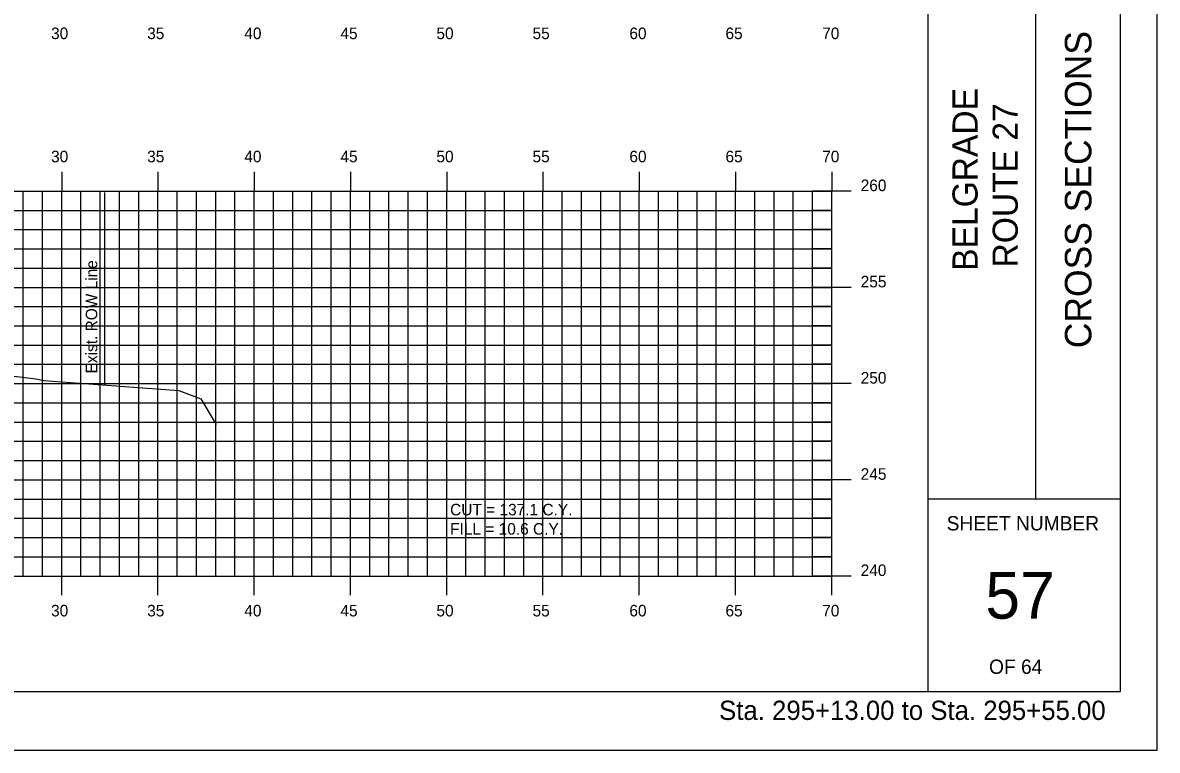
# Model space of a CAD drawing. Extents: x 859575 to 859745, y 366268 to 366378.
# Drawn here: x 859685.8 to 859744.7, y 366268.2 to 366306 of the extents above; entities that cross this region are included whole.
import ezdxf

# ---------------------------------------------------------------- set-up
doc = ezdxf.new("R2010")
doc.units = 0
for name, color, linetype in [('ANNOTATION', 7, 'Continuous'), ('BORDER', 7, 'Continuous'), ('E_ROW_Line', 7, 'Continuous'), ('H_V ANNOTATION', 7, 'Continuous'), ('HIGHWAY_TITLE', 7, 'Continuous'), ('MAJOR', 7, 'Continuous'), ('MINOR', 7, 'Continuous'), ('PLOT BOUNDARY', 7, 'Continuous'), ('S_Roadway_Centerline', 7, 'Continuous')]:
    doc.layers.add(name, color=color, linetype=linetype)

msp = doc.modelspace()

# ---------------------------------------------------------------- linework, layer by layer
at = {"layer": 'BORDER'}
for p, q in [((859732.797, 366271.236), (859732.797, 366376.239)), ((859742.797, 366271.236), (859742.797, 366376.236)), ((859738.388, 366281.239), (859738.388, 366316.239)), ((859732.797, 366281.239), (859742.797, 366281.239)), ((859582.797, 366271.236), (859742.797, 366271.236))]:
    msp.add_line(p, q, dxfattribs=at)
at = {"layer": 'E_ROW_Line'}
msp.add_line((859690.047, 366287.162), (859690.047, 366297.162), dxfattribs=at)
at = {"layer": 'MAJOR'}
for p, q in [((859687.797, 366298.238), (859687.797, 366297.236)), ((859692.797, 366298.238), (859692.797, 366297.236)), ((859697.797, 366298.238), (859697.797, 366297.236)), ((859702.797, 366298.238), (859702.797, 366297.236)), ((859707.797, 366298.238), (859707.797, 366297.236)), ((859712.797, 366298.238), (859712.797, 366297.236)), ((859717.797, 366298.238), (859717.797, 366297.236)), ((859722.797, 366298.238), (859722.797, 366297.236)), ((859727.797, 366298.238), (859727.797, 366297.236)), ((859587.797, 366297.236), (859727.797, 366297.236)), ((859587.797, 366297.236), (859727.797, 366297.236)), ((859687.797, 366277.236), (859687.797, 366297.236)), ((859692.797, 366277.236), (859692.797, 366297.236)), ((859697.797, 366277.236), (859697.797, 366297.236)), ((859702.797, 366277.236), (859702.797, 366297.236)), ((859707.797, 366277.236), (859707.797, 366297.236)), ((859712.797, 366277.236), (859712.797, 366297.236)), ((859717.797, 366277.236), (859717.797, 366297.236)), ((859722.797, 366277.236), (859722.797, 366297.236)), ((859728.799, 366297.236), (859726.795, 366297.236)), ((859727.797, 366277.236), (859727.797, 366297.236)), ((859727.797, 366277.236), (859727.797, 366297.236)), ((859587.797, 366292.236), (859727.797, 366292.236)), ((859728.799, 366292.236), (859726.795, 366292.236)), ((859587.797, 366287.236), (859727.797, 366287.236)), ((859728.799, 366287.236), (859726.795, 366287.236)), ((859587.797, 366282.236), (859727.797, 366282.236)), ((859728.799, 366282.236), (859726.795, 366282.236)), ((859587.797, 366277.236), (859727.797, 366277.236)), ((859587.797, 366277.236), (859727.797, 366277.236)), ((859687.797, 366276.234), (859687.797, 366277.236)), ((859692.797, 366276.234), (859692.797, 366277.236)), ((859697.797, 366276.234), (859697.797, 366277.236)), ((859702.797, 366276.234), (859702.797, 366277.236)), ((859707.797, 366276.234), (859707.797, 366277.236)), ((859712.797, 366276.234), (859712.797, 366277.236)), ((859717.797, 366276.234), (859717.797, 366277.236)), ((859722.797, 366276.234), (859722.797, 366277.236)), ((859728.799, 366277.236), (859726.795, 366277.236)), ((859727.797, 366276.234), (859727.797, 366277.236))]:
    msp.add_line(p, q, dxfattribs=at)
at = {"layer": 'MINOR'}
for p, q in [((859685.797, 366277.236), (859685.797, 366297.236)), ((859686.797, 366277.236), (859686.797, 366297.236)), ((859688.797, 366277.236), (859688.797, 366297.236)), ((859689.797, 366277.236), (859689.797, 366297.236)), ((859690.797, 366277.236), (859690.797, 366297.236)), ((859691.797, 366277.236), (859691.797, 366297.236)), ((859693.797, 366277.236), (859693.797, 366297.236)), ((859694.797, 366277.236), (859694.797, 366297.236)), ((859695.797, 366277.236), (859695.797, 366297.236)), ((859696.797, 366277.236), (859696.797, 366297.236)), ((859698.797, 366277.236), (859698.797, 366297.236)), ((859699.797, 366277.236), (859699.797, 366297.236)), ((859700.797, 366277.236), (859700.797, 366297.236)), ((859701.797, 366277.236), (859701.797, 366297.236)), ((859703.797, 366277.236), (859703.797, 366297.236)), ((859704.797, 366277.236), (859704.797, 366297.236)), ((859705.797, 366277.236), (859705.797, 366297.236)), ((859706.797, 366277.236), (859706.797, 366297.236)), ((859708.797, 366277.236), (859708.797, 366297.236)), ((859709.797, 366277.236), (859709.797, 366297.236)), ((859710.797, 366277.236), (859710.797, 366297.236)), ((859711.797, 366277.236), (859711.797, 366297.236)), ((859713.797, 366277.236), (859713.797, 366297.236)), ((859714.797, 366277.236), (859714.797, 366297.236)), ((859715.797, 366277.236), (859715.797, 366297.236)), ((859716.797, 366277.236), (859716.797, 366297.236)), ((859718.797, 366277.236), (859718.797, 366297.236)), ((859719.797, 366277.236), (859719.797, 366297.236)), ((859720.797, 366277.236), (859720.797, 366297.236)), ((859721.797, 366277.236), (859721.797, 366297.236)), ((859723.797, 366277.236), (859723.797, 366297.236)), ((859724.797, 366277.236), (859724.797, 366297.236)), ((859725.797, 366277.236), (859725.797, 366297.236)), ((859726.797, 366277.236), (859726.797, 366297.236)), ((859587.797, 366296.236), (859727.797, 366296.236)), ((859727.797, 366296.236), (859726.795, 366296.236)), ((859587.797, 366295.236), (859727.797, 366295.236)), ((859727.797, 366295.236), (859726.795, 366295.236)), ((859587.797, 366294.236), (859727.797, 366294.236)), ((859727.797, 366294.236), (859726.795, 366294.236)), ((859587.797, 366293.236), (859727.797, 366293.236)), ((859727.797, 366293.236), (859726.795, 366293.236)), ((859587.797, 366291.236), (859727.797, 366291.236)), ((859727.797, 366291.236), (859726.795, 366291.236)), ((859587.797, 366290.236), (859727.797, 366290.236)), ((859727.797, 366290.236), (859726.795, 366290.236)), ((859587.797, 366289.236), (859727.797, 366289.236)), ((859727.797, 366289.236), (859726.795, 366289.236)), ((859587.797, 366288.236), (859727.797, 366288.236)), ((859727.797, 366288.236), (859726.795, 366288.236)), ((859587.797, 366286.236), (859727.797, 366286.236)), ((859727.797, 366286.236), (859726.795, 366286.236)), ((859587.797, 366285.236), (859727.797, 366285.236)), ((859727.797, 366285.236), (859726.795, 366285.236)), ((859587.797, 366284.236), (859727.797, 366284.236)), ((859727.797, 366284.236), (859726.795, 366284.236)), ((859587.797, 366283.236), (859727.797, 366283.236)), ((859727.797, 366283.236), (859726.795, 366283.236)), ((859587.797, 366281.236), (859727.797, 366281.236)), ((859727.797, 366281.236), (859726.795, 366281.236)), ((859587.797, 366280.236), (859727.797, 366280.236)), ((859727.797, 366280.236), (859726.795, 366280.236)), ((859587.797, 366279.236), (859727.797, 366279.236)), ((859727.797, 366279.236), (859726.795, 366279.236)), ((859587.797, 366278.236), (859727.797, 366278.236)), ((859727.797, 366278.236), (859726.795, 366278.236))]:
    msp.add_line(p, q, dxfattribs=at)
at = {"layer": 'PLOT BOUNDARY'}
msp.add_lwpolyline([(859574.704, 366268.177), (859744.704, 366268.177), (859744.704, 366378.177), (859574.704, 366378.177)], close=True, dxfattribs=at)
at = {"layer": 'S_Roadway_Centerline'}
msp.add_lwpolyline([(859680.477, 366288.214), (859686.457, 366287.48), (859686.873, 366287.399), (859686.873, 366287.399), (859693.885, 366286.877), (859695.021, 366286.438), (859695.825, 366285.109)], dxfattribs=at)

# ---------------------------------------------------------------- texts
at = {"layer": 'ANNOTATION'}
for s, p in [('CUT = 137.1 C.Y.', (859707.973, 366280.386)), ('FILL = 10.6 C.Y.', (859707.973, 366279.384))]:
    msp.add_text(s, height=0.6, dxfattribs=at).set_placement(p)
at = {"layer": 'BORDER'}
for s, height, rotation, p in [('CROSS SECTIONS', 1.37787, 90, (859741.282, 366289.073)), ('SHEET NUMBER', 0.74527, 360, (859733.763, 366279.603)), ('57', 2.4194, 360, (859735.773, 366275.019)), ('OF 64', 0.7453, 360, (859735.964, 366272.149))]:
    msp.add_text(s, height=height, rotation=rotation, dxfattribs=at).set_placement(p)
at = {"layer": 'E_ROW_Line'}
msp.add_text('Exist. ROW Line', height=0.6, rotation=90, dxfattribs=at).set_placement((859689.647, 366287.762))
at = {"layer": 'H_V ANNOTATION'}
for s, height, p in [('30', 0.6, (859687.246, 366305.136)), ('35', 0.6, (859692.238, 366305.136)), ('40', 0.6, (859697.283, 366305.136)), ('45', 0.6, (859702.275, 366305.136)), ('50', 0.6, (859707.262, 366305.136)), ('55', 0.6, (859712.254, 366305.136)), ('60', 0.6, (859717.283, 366305.136)), ('65', 0.6, (859722.275, 366305.136)), ('70', 0.6, (859727.299, 366305.136)), ('30', 0.6, (859687.246, 366298.736)), ('35', 0.6, (859692.238, 366298.736)), ('40', 0.6, (859697.283, 366298.736)), ('45', 0.6, (859702.275, 366298.736)), ('50', 0.6, (859707.262, 366298.736)), ('55', 0.6, (859712.254, 366298.736)), ('60', 0.6, (859717.283, 366298.736)), ('65', 0.6, (859722.275, 366298.736)), ('70', 0.6, (859727.299, 366298.736)), ('260', 0.6, (859729.297, 366297.236)), ('255', 0.6, (859729.297, 366292.236)), ('250', 0.6, (859729.297, 366287.236)), ('245', 0.6, (859729.297, 366282.236)), ('240', 0.6, (859729.297, 366277.236)), ('30', 0.6, (859687.246, 366275.136)), ('35', 0.6, (859692.238, 366275.136)), ('40', 0.6, (859697.283, 366275.136)), ('45', 0.6, (859702.275, 366275.136)), ('50', 0.6, (859707.262, 366275.136)), ('55', 0.6, (859712.254, 366275.136)), ('60', 0.6, (859717.283, 366275.136)), ('65', 0.6, (859722.275, 366275.136)), ('70', 0.6, (859727.299, 366275.136)), ('Sta. 295+13.00 to Sta. 295+55.00', 1.0002, (859721.943, 366269.756))]:
    msp.add_text(s, height=height, dxfattribs=at).set_placement(p)
at = {"layer": 'HIGHWAY_TITLE'}
for s, p in [('BELGRADE', (859735.37, 366293.095)), ('ROUTE 27', (859737.457, 366293.269))]:
    msp.add_text(s, height=1.3043, rotation=90, dxfattribs=at).set_placement(p)

doc.saveas('drawing.dxf')
